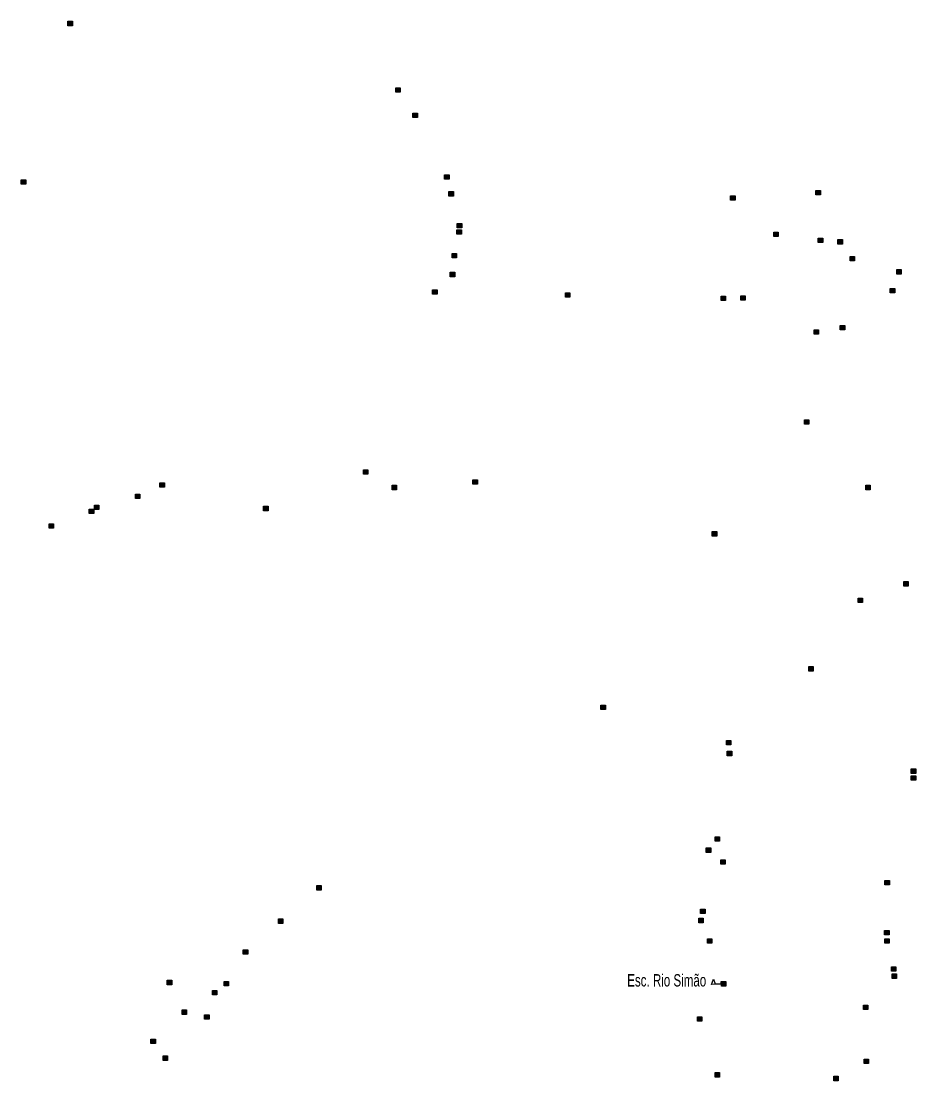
# Model space of a CAD drawing. Extents: x 649.2 to 674.4, y 7040 to 7068.1.
# Drawn here: x 668.33 to 674.13, y 7047.08 to 7053.95 of the extents above; entities that cross this region are included whole.
import ezdxf
from ezdxf.enums import TextEntityAlignment as Align

# ---------------------------------------------------------------- set-up
doc = ezdxf.new("R2010")
doc.units = 0
doc.header["$LTSCALE"] = 0.032
doc.layers.add('2', color=7, linetype='Continuous', lineweight=25)
doc.layers.add('4', color=7, linetype='Continuous', lineweight=25)
doc.layers.add('61', color=7, linetype='Continuous')

msp = doc.modelspace()

# ---------------------------------------------------------------- hatches: boundary and pattern name
at = {"layer": '2'}
for points in [[(668.6374, 7053.9457), (668.6664, 7053.9457), (668.6664, 7053.9167), (668.6374, 7053.9167)], [(670.7611, 7053.5139), (670.7901, 7053.5139), (670.7901, 7053.4849), (670.7611, 7053.4849)], [(670.8727, 7053.3498), (670.9017, 7053.3498), (670.9017, 7053.3208), (670.8727, 7053.3208)], [(671.0779, 7052.9501), (671.1069, 7052.9501), (671.1069, 7052.9211), (671.0779, 7052.9211)], [(668.3343, 7052.9178), (668.3633, 7052.9178), (668.3633, 7052.8888), (668.3343, 7052.8888)], [(671.1055, 7052.8411), (671.1345, 7052.8411), (671.1345, 7052.8121), (671.1055, 7052.8121)], [(672.9303, 7052.8139), (672.9593, 7052.8139), (672.9593, 7052.7849), (672.9303, 7052.7849)], [(673.4834, 7052.8492), (673.5124, 7052.8492), (673.5124, 7052.8202), (673.4834, 7052.8202)], [(671.1574, 7052.5938), (671.1864, 7052.5938), (671.1864, 7052.5648), (671.1574, 7052.5648)], [(671.1591, 7052.6353), (671.1881, 7052.6353), (671.1881, 7052.6063), (671.1591, 7052.6063)], [(673.2106, 7052.5782), (673.2396, 7052.5782), (673.2396, 7052.5492), (673.2106, 7052.5492)], [(673.4982, 7052.5393), (673.5272, 7052.5393), (673.5272, 7052.5103), (673.4982, 7052.5103)], [(673.6263, 7052.53), (673.6553, 7052.53), (673.6553, 7052.501), (673.6263, 7052.501)], [(671.1263, 7052.4399), (671.1553, 7052.4399), (671.1553, 7052.4109), (671.1263, 7052.4109)], [(673.7042, 7052.4205), (673.7332, 7052.4205), (673.7332, 7052.3915), (673.7042, 7052.3915)], [(671.1142, 7052.3188), (671.1432, 7052.3188), (671.1432, 7052.2898), (671.1142, 7052.2898)], [(674.007, 7052.3353), (674.036, 7052.3353), (674.036, 7052.3063), (674.007, 7052.3063)], [(671, 7052.2046), (671.029, 7052.2046), (671.029, 7052.1756), (671, 7052.1756)], [(671.8608, 7052.1858), (671.8898, 7052.1858), (671.8898, 7052.1568), (671.8608, 7052.1568)], [(673.9646, 7052.2134), (673.9936, 7052.2134), (673.9936, 7052.1844), (673.9646, 7052.1844)], [(672.8695, 7052.1641), (672.8985, 7052.1641), (672.8985, 7052.1351), (672.8695, 7052.1351)], [(672.9969, 7052.1658), (673.0259, 7052.1658), (673.0259, 7052.1368), (672.9969, 7052.1368)], [(673.6414, 7051.9741), (673.6704, 7051.9741), (673.6704, 7051.9451), (673.6414, 7051.9451)], [(673.4716, 7051.9461), (673.5006, 7051.9461), (673.5006, 7051.9171), (673.4716, 7051.9171)], [(673.409, 7051.3624), (673.438, 7051.3624), (673.438, 7051.3334), (673.409, 7051.3334)], [(670.5511, 7051.0386), (670.5801, 7051.0386), (670.5801, 7051.0096), (670.5511, 7051.0096)], [(669.2328, 7050.9541), (669.2618, 7050.9541), (669.2618, 7050.9251), (669.2328, 7050.9251)], [(670.7371, 7050.9377), (670.7661, 7050.9377), (670.7661, 7050.9087), (670.7371, 7050.9087)], [(671.2613, 7050.9736), (671.2903, 7050.9736), (671.2903, 7050.9446), (671.2613, 7050.9446)], [(673.8061, 7050.9383), (673.8351, 7050.9383), (673.8351, 7050.9093), (673.8061, 7050.9093)], [(669.075, 7050.8811), (669.104, 7050.8811), (669.104, 7050.8521), (669.075, 7050.8521)], [(668.8087, 7050.8092), (668.8377, 7050.8092), (668.8377, 7050.7802), (668.8087, 7050.7802)], [(669.9045, 7050.8018), (669.9335, 7050.8018), (669.9335, 7050.7728), (669.9045, 7050.7728)], [(668.7757, 7050.7833), (668.8047, 7050.7833), (668.8047, 7050.7543), (668.7757, 7050.7543)], [(668.5153, 7050.6879), (668.5443, 7050.6879), (668.5443, 7050.6589), (668.5153, 7050.6589)], [(672.8114, 7050.6376), (672.8404, 7050.6376), (672.8404, 7050.6086), (672.8114, 7050.6086)], [(674.0522, 7050.3139), (674.0812, 7050.3139), (674.0812, 7050.2849), (674.0522, 7050.2849)], [(673.7566, 7050.2065), (673.7856, 7050.2065), (673.7856, 7050.1775), (673.7566, 7050.1775)], [(673.4363, 7049.7625), (673.4653, 7049.7625), (673.4653, 7049.7335), (673.4363, 7049.7335)], [(672.0903, 7049.5134), (672.1193, 7049.5134), (672.1193, 7049.4844), (672.0903, 7049.4844)], [(672.903, 7049.2835), (672.932, 7049.2835), (672.932, 7049.2545), (672.903, 7049.2545)], [(672.9087, 7049.2138), (672.9377, 7049.2138), (672.9377, 7049.1848), (672.9087, 7049.1848)], [(674.1014, 7049.0997), (674.1304, 7049.0997), (674.1304, 7049.0707), (674.1014, 7049.0707)], [(674.101, 7049.0553), (674.13, 7049.0553), (674.13, 7049.0263), (674.101, 7049.0263)], [(672.8306, 7048.6597), (672.8596, 7048.6597), (672.8596, 7048.6307), (672.8306, 7048.6307)], [(672.7731, 7048.5875), (672.8021, 7048.5875), (672.8021, 7048.5585), (672.7731, 7048.5585)], [(672.8665, 7048.5104), (672.8955, 7048.5104), (672.8955, 7048.4814), (672.8665, 7048.4814)], [(670.2496, 7048.3436), (670.2786, 7048.3436), (670.2786, 7048.3146), (670.2496, 7048.3146)], [(673.93, 7048.3761), (673.959, 7048.3761), (673.959, 7048.3471), (673.93, 7048.3471)], [(672.7364, 7048.1909), (672.7654, 7048.1909), (672.7654, 7048.1619), (672.7364, 7048.1619)], [(670.0007, 7048.1274), (670.0297, 7048.1274), (670.0297, 7048.0984), (670.0007, 7048.0984)], [(672.724, 7048.1315), (672.753, 7048.1315), (672.753, 7048.1025), (672.724, 7048.1025)], [(673.9282, 7048.0526), (673.9572, 7048.0526), (673.9572, 7048.0236), (673.9282, 7048.0236)], [(672.7805, 7047.9982), (672.8095, 7047.9982), (672.8095, 7047.9692), (672.7805, 7047.9692)], [(673.9291, 7047.9985), (673.9581, 7047.9985), (673.9581, 7047.9695), (673.9291, 7047.9695)], [(669.7732, 7047.9269), (669.8022, 7047.9269), (669.8022, 7047.8979), (669.7732, 7047.8979)], [(673.9725, 7047.8166), (674.0015, 7047.8166), (674.0015, 7047.7876), (673.9725, 7047.7876)], [(669.2806, 7047.7296), (669.3096, 7047.7296), (669.3096, 7047.7006), (669.2806, 7047.7006)], [(669.6489, 7047.7225), (669.6779, 7047.7225), (669.6779, 7047.6935), (669.6489, 7047.6935)], [(673.9772, 7047.7707), (674.0062, 7047.7707), (674.0062, 7047.7417), (673.9772, 7047.7417)], [(669.5736, 7047.6632), (669.6026, 7047.6632), (669.6026, 7047.6342), (669.5736, 7047.6342)], [(673.7911, 7047.5692), (673.8201, 7047.5692), (673.8201, 7047.5402), (673.7911, 7047.5402)], [(669.3771, 7047.5375), (669.4061, 7047.5375), (669.4061, 7047.5085), (669.3771, 7047.5085)], [(669.5223, 7047.5056), (669.5513, 7047.5056), (669.5513, 7047.4766), (669.5223, 7047.4766)], [(672.7157, 7047.4925), (672.7447, 7047.4925), (672.7447, 7047.4635), (672.7157, 7047.4635)], [(669.1744, 7047.348), (669.2034, 7047.348), (669.2034, 7047.319), (669.1744, 7047.319)], [(669.254, 7047.2394), (669.283, 7047.2394), (669.283, 7047.2104), (669.254, 7047.2104)], [(673.7958, 7047.2182), (673.8248, 7047.2182), (673.8248, 7047.1892), (673.7958, 7047.1892)], [(672.8295, 7047.1315), (672.8585, 7047.1315), (672.8585, 7047.1025), (672.8295, 7047.1025)], [(673.5993, 7047.107), (673.6283, 7047.107), (673.6283, 7047.078), (673.5993, 7047.078)]]:
    msp.add_hatch(color=256, dxfattribs=at).paths.add_polyline_path(points)
at = {"layer": '4'}
msp.add_hatch(color=256, dxfattribs=at).paths.add_polyline_path([(672.9006, 7047.6917), (672.8707, 7047.6908), (672.8697, 7047.7208), (672.8997, 7047.7217)])

# ---------------------------------------------------------------- linework, layer by layer
at = {"layer": '2'}
for points in [[(668.6374, 7053.9457), (668.6664, 7053.9457), (668.6664, 7053.9167), (668.6374, 7053.9167)], [(670.7611, 7053.5139), (670.7901, 7053.5139), (670.7901, 7053.4849), (670.7611, 7053.4849)], [(670.8727, 7053.3498), (670.9017, 7053.3498), (670.9017, 7053.3208), (670.8727, 7053.3208)], [(671.0779, 7052.9501), (671.1069, 7052.9501), (671.1069, 7052.9211), (671.0779, 7052.9211)], [(668.3343, 7052.9178), (668.3633, 7052.9178), (668.3633, 7052.8888), (668.3343, 7052.8888)], [(671.1055, 7052.8411), (671.1345, 7052.8411), (671.1345, 7052.8121), (671.1055, 7052.8121)], [(672.9303, 7052.8139), (672.9593, 7052.8139), (672.9593, 7052.7849), (672.9303, 7052.7849)], [(673.4834, 7052.8492), (673.5124, 7052.8492), (673.5124, 7052.8202), (673.4834, 7052.8202)], [(671.1574, 7052.5938), (671.1864, 7052.5938), (671.1864, 7052.5648), (671.1574, 7052.5648)], [(671.1591, 7052.6353), (671.1881, 7052.6353), (671.1881, 7052.6063), (671.1591, 7052.6063)], [(673.2106, 7052.5782), (673.2396, 7052.5782), (673.2396, 7052.5492), (673.2106, 7052.5492)], [(673.4982, 7052.5393), (673.5272, 7052.5393), (673.5272, 7052.5103), (673.4982, 7052.5103)], [(673.6263, 7052.53), (673.6553, 7052.53), (673.6553, 7052.501), (673.6263, 7052.501)], [(671.1263, 7052.4399), (671.1553, 7052.4399), (671.1553, 7052.4109), (671.1263, 7052.4109)], [(673.7042, 7052.4205), (673.7332, 7052.4205), (673.7332, 7052.3915), (673.7042, 7052.3915)], [(671.1142, 7052.3188), (671.1432, 7052.3188), (671.1432, 7052.2898), (671.1142, 7052.2898)], [(674.007, 7052.3353), (674.036, 7052.3353), (674.036, 7052.3063), (674.007, 7052.3063)], [(671, 7052.2046), (671.029, 7052.2046), (671.029, 7052.1756), (671, 7052.1756)], [(671.8608, 7052.1858), (671.8898, 7052.1858), (671.8898, 7052.1568), (671.8608, 7052.1568)], [(673.9646, 7052.2134), (673.9936, 7052.2134), (673.9936, 7052.1844), (673.9646, 7052.1844)], [(672.8695, 7052.1641), (672.8985, 7052.1641), (672.8985, 7052.1351), (672.8695, 7052.1351)], [(672.9969, 7052.1658), (673.0259, 7052.1658), (673.0259, 7052.1368), (672.9969, 7052.1368)], [(673.6414, 7051.9741), (673.6704, 7051.9741), (673.6704, 7051.9451), (673.6414, 7051.9451)], [(673.4716, 7051.9461), (673.5006, 7051.9461), (673.5006, 7051.9171), (673.4716, 7051.9171)], [(673.409, 7051.3624), (673.438, 7051.3624), (673.438, 7051.3334), (673.409, 7051.3334)], [(670.5511, 7051.0386), (670.5801, 7051.0386), (670.5801, 7051.0096), (670.5511, 7051.0096)], [(669.2328, 7050.9541), (669.2618, 7050.9541), (669.2618, 7050.9251), (669.2328, 7050.9251)], [(670.7371, 7050.9377), (670.7661, 7050.9377), (670.7661, 7050.9087), (670.7371, 7050.9087)], [(671.2613, 7050.9736), (671.2903, 7050.9736), (671.2903, 7050.9446), (671.2613, 7050.9446)], [(673.8061, 7050.9383), (673.8351, 7050.9383), (673.8351, 7050.9093), (673.8061, 7050.9093)], [(669.075, 7050.8811), (669.104, 7050.8811), (669.104, 7050.8521), (669.075, 7050.8521)], [(668.8087, 7050.8092), (668.8377, 7050.8092), (668.8377, 7050.7802), (668.8087, 7050.7802)], [(669.9045, 7050.8018), (669.9335, 7050.8018), (669.9335, 7050.7728), (669.9045, 7050.7728)], [(668.7757, 7050.7833), (668.8047, 7050.7833), (668.8047, 7050.7543), (668.7757, 7050.7543)], [(668.5153, 7050.6879), (668.5443, 7050.6879), (668.5443, 7050.6589), (668.5153, 7050.6589)], [(672.8114, 7050.6376), (672.8404, 7050.6376), (672.8404, 7050.6086), (672.8114, 7050.6086)], [(674.0522, 7050.3139), (674.0812, 7050.3139), (674.0812, 7050.2849), (674.0522, 7050.2849)], [(673.7566, 7050.2065), (673.7856, 7050.2065), (673.7856, 7050.1775), (673.7566, 7050.1775)], [(673.4363, 7049.7625), (673.4653, 7049.7625), (673.4653, 7049.7335), (673.4363, 7049.7335)], [(672.0903, 7049.5134), (672.1193, 7049.5134), (672.1193, 7049.4844), (672.0903, 7049.4844)], [(672.903, 7049.2835), (672.932, 7049.2835), (672.932, 7049.2545), (672.903, 7049.2545)], [(672.9087, 7049.2138), (672.9377, 7049.2138), (672.9377, 7049.1848), (672.9087, 7049.1848)], [(674.1014, 7049.0997), (674.1304, 7049.0997), (674.1304, 7049.0707), (674.1014, 7049.0707)], [(674.101, 7049.0553), (674.13, 7049.0553), (674.13, 7049.0263), (674.101, 7049.0263)], [(672.8306, 7048.6597), (672.8596, 7048.6597), (672.8596, 7048.6307), (672.8306, 7048.6307)], [(672.7731, 7048.5875), (672.8021, 7048.5875), (672.8021, 7048.5585), (672.7731, 7048.5585)], [(672.8665, 7048.5104), (672.8955, 7048.5104), (672.8955, 7048.4814), (672.8665, 7048.4814)], [(670.2496, 7048.3436), (670.2786, 7048.3436), (670.2786, 7048.3146), (670.2496, 7048.3146)], [(673.93, 7048.3761), (673.959, 7048.3761), (673.959, 7048.3471), (673.93, 7048.3471)], [(672.7364, 7048.1909), (672.7654, 7048.1909), (672.7654, 7048.1619), (672.7364, 7048.1619)], [(670.0007, 7048.1274), (670.0297, 7048.1274), (670.0297, 7048.0984), (670.0007, 7048.0984)], [(672.724, 7048.1315), (672.753, 7048.1315), (672.753, 7048.1025), (672.724, 7048.1025)], [(673.9282, 7048.0526), (673.9572, 7048.0526), (673.9572, 7048.0236), (673.9282, 7048.0236)], [(672.7805, 7047.9982), (672.8095, 7047.9982), (672.8095, 7047.9692), (672.7805, 7047.9692)], [(673.9291, 7047.9985), (673.9581, 7047.9985), (673.9581, 7047.9695), (673.9291, 7047.9695)], [(669.7732, 7047.9269), (669.8022, 7047.9269), (669.8022, 7047.8979), (669.7732, 7047.8979)], [(673.9725, 7047.8166), (674.0015, 7047.8166), (674.0015, 7047.7876), (673.9725, 7047.7876)], [(669.2806, 7047.7296), (669.3096, 7047.7296), (669.3096, 7047.7006), (669.2806, 7047.7006)], [(669.6489, 7047.7225), (669.6779, 7047.7225), (669.6779, 7047.6935), (669.6489, 7047.6935)], [(673.9772, 7047.7707), (674.0062, 7047.7707), (674.0062, 7047.7417), (673.9772, 7047.7417)], [(669.5736, 7047.6632), (669.6026, 7047.6632), (669.6026, 7047.6342), (669.5736, 7047.6342)], [(673.7911, 7047.5692), (673.8201, 7047.5692), (673.8201, 7047.5402), (673.7911, 7047.5402)], [(669.3771, 7047.5375), (669.4061, 7047.5375), (669.4061, 7047.5085), (669.3771, 7047.5085)], [(669.5223, 7047.5056), (669.5513, 7047.5056), (669.5513, 7047.4766), (669.5223, 7047.4766)], [(672.7157, 7047.4925), (672.7447, 7047.4925), (672.7447, 7047.4635), (672.7157, 7047.4635)], [(669.1744, 7047.348), (669.2034, 7047.348), (669.2034, 7047.319), (669.1744, 7047.319)], [(669.254, 7047.2394), (669.283, 7047.2394), (669.283, 7047.2104), (669.254, 7047.2104)], [(673.7958, 7047.2182), (673.8248, 7047.2182), (673.8248, 7047.1892), (673.7958, 7047.1892)], [(672.8295, 7047.1315), (672.8585, 7047.1315), (672.8585, 7047.1025), (672.8295, 7047.1025)], [(673.5993, 7047.107), (673.6283, 7047.107), (673.6283, 7047.078), (673.5993, 7047.078)]]:
    msp.add_lwpolyline(points, close=True, dxfattribs=at)
at = {"layer": '4'}
msp.add_line((672.8703, 7047.7033), (672.8701, 7047.7083), dxfattribs=at)
for points in [[(672.8703, 7047.7033), (672.8078, 7047.7013), (672.8192, 7047.7367), (672.8306, 7047.707), (672.8701, 7047.7083)], [(672.9006, 7047.6917), (672.8707, 7047.6908), (672.8697, 7047.7208), (672.8997, 7047.7217)]]:
    msp.add_lwpolyline(points, close=True, dxfattribs=at)

# ---------------------------------------------------------------- texts
at = {"layer": '61', "width": 0.7}
msp.add_text('Esc. Rio Simão', height=0.08, dxfattribs=at).set_placement((672.7725, 7047.6892), align=Align.RIGHT)

doc.saveas('drawing.dxf')
